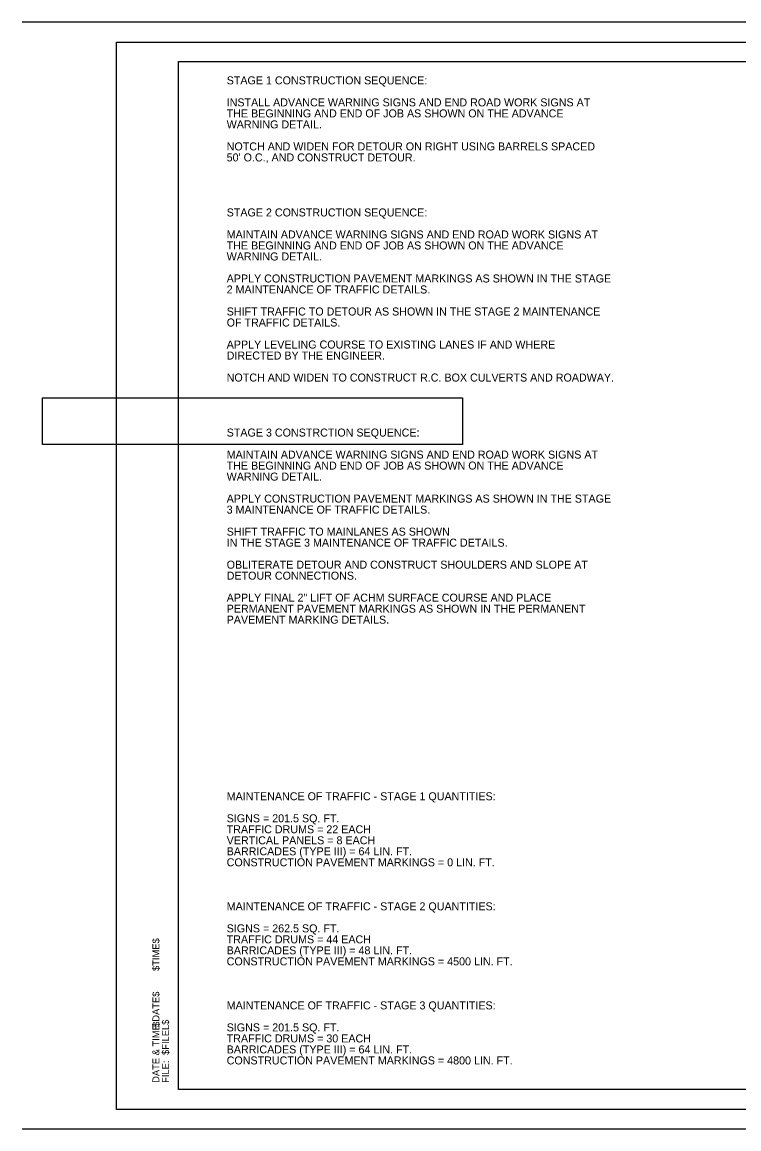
# Model space of a CAD drawing. Extents: x 6125 to 14104, y 8730 to 11067.
# Drawn here: x 6125 to 6841, y 9961 to 11067 of the extents above; entities that cross this region are included whole.
import ezdxf

# ---------------------------------------------------------------- set-up
doc = ezdxf.new("R2010")
doc.units = 0
doc.layers.add('GREEN_TXT', color=7, linetype='Continuous')
doc.layers.add('SEAL-INFO', color=7, linetype='Continuous')

msp = doc.modelspace()

# ---------------------------------------------------------------- linework, layer by layer
msp.add_lwpolyline([(6145.7, 10691.1), (6565.1, 10691.1), (6565.1, 10644.6), (6145.7, 10644.6)], close=True)
at = {"layer": 'GREEN_TXT'}
for p, q in [((7885.4, 11066.7), (6125.4, 11066.7)), ((6281.5, 11027.3), (7862.4, 11027.3)), ((6281.5, 10000), (6281.5, 11027.3)), ((7862.4, 10000), (6281.5, 10000)), ((6125.4, 9960.6), (7885.4, 9960.6))]:
    msp.add_line(p, q, dxfattribs=at)
at = {"layer": 'SEAL-INFO'}
msp.add_lwpolyline([(6219.5, 11046.8), (7886.2, 11046.8), (7886.2, 9980.1), (6219.5, 9980.1)], close=True, dxfattribs=at)

# ---------------------------------------------------------------- texts
for s, p in [('STAGE 1 CONSTRUCTION SEQUENCE:', (6329.7, 11004.5)), ('INSTALL ADVANCE WARNING SIGNS AND END ROAD WORK SIGNS AT ', (6329.7, 10982.5)), ('THE BEGINNING AND END OF JOB AS SHOWN ON THE ADVANCE ', (6329.7, 10971.5)), ('WARNING DETAIL.', (6329.7, 10960.5)), ('NOTCH AND WIDEN FOR DETOUR ON RIGHT USING BARRELS SPACED ', (6329.7, 10938.5)), ("50' O.C., AND CONSTRUCT DETOUR.", (6329.7, 10927.5)), ('STAGE 2 CONSTRUCTION SEQUENCE:', (6329.7, 10872.5)), ('MAINTAIN ADVANCE WARNING SIGNS AND END ROAD WORK SIGNS AT ', (6329.7, 10850.5)), ('THE BEGINNING AND END OF JOB AS SHOWN ON THE ADVANCE ', (6329.7, 10839.5)), ('WARNING DETAIL.', (6329.7, 10828.5)), ('APPLY CONSTRUCTION PAVEMENT MARKINGS AS SHOWN IN THE STAGE ', (6329.7, 10806.5)), ('2 MAINTENANCE OF TRAFFIC DETAILS.', (6329.7, 10795.5)), ('SHIFT TRAFFIC TO DETOUR AS SHOWN IN THE STAGE 2 MAINTENANCE ', (6329.7, 10773.5)), ('OF TRAFFIC DETAILS.', (6329.7, 10762.5)), ('APPLY LEVELING COURSE TO EXISTING LANES IF AND WHERE ', (6329.7, 10740.5)), ('DIRECTED BY THE ENGINEER.', (6329.7, 10729.5)), ('NOTCH AND WIDEN TO CONSTRUCT R.C. BOX CULVERTS AND ROADWAY.', (6329.7, 10707.5)), ('STAGE 3 CONSTRCTION SEQUENCE:', (6329.7, 10652.5)), ('MAINTAIN ADVANCE WARNING SIGNS AND END ROAD WORK SIGNS AT ', (6329.7, 10630.5)), ('THE BEGINNING AND END OF JOB AS SHOWN ON THE ADVANCE ', (6329.7, 10619.5)), ('WARNING DETAIL.', (6329.7, 10608.5)), ('APPLY CONSTRUCTION PAVEMENT MARKINGS AS SHOWN IN THE STAGE ', (6329.7, 10586.5)), ('3 MAINTENANCE OF TRAFFIC DETAILS.', (6329.7, 10575.5)), ('SHIFT TRAFFIC TO MAINLANES AS SHOWN', (6329.7, 10553.5)), ('IN THE STAGE 3 MAINTENANCE OF TRAFFIC DETAILS.', (6329.7, 10542.5)), ('OBLITERATE DETOUR AND CONSTRUCT SHOULDERS AND SLOPE AT ', (6329.7, 10520.5)), ('DETOUR CONNECTIONS.', (6329.7, 10509.5)), ('APPLY FINAL 2" LIFT OF ACHM SURFACE COURSE AND PLACE ', (6329.7, 10487.5)), ('PERMANENT PAVEMENT MARKINGS AS SHOWN IN THE PERMANENT ', (6329.7, 10476.5)), ('PAVEMENT MARKING DETAILS.', (6329.7, 10465.5)), ('MAINTENANCE OF TRAFFIC - STAGE 1 QUANTITIES:', (6329.7, 10289)), ('SIGNS = 201.5 SQ. FT.', (6329.7, 10267)), ('TRAFFIC DRUMS = 22 EACH', (6329.7, 10256)), ('VERTICAL PANELS = 8 EACH', (6329.7, 10245)), ('BARRICADES (TYPE III) = 64 LIN. FT.', (6329.7, 10234)), ('CONSTRUCTION PAVEMENT MARKINGS = 0 LIN. FT.', (6329.7, 10223)), ('MAINTENANCE OF TRAFFIC - STAGE 2 QUANTITIES:', (6329.7, 10179)), ('SIGNS = 262.5 SQ. FT.', (6329.7, 10157)), ('TRAFFIC DRUMS = 44 EACH', (6329.7, 10146)), ('BARRICADES (TYPE III) = 48 LIN. FT.', (6329.7, 10135)), ('CONSTRUCTION PAVEMENT MARKINGS = 4500 LIN. FT.', (6329.7, 10124)), ('MAINTENANCE OF TRAFFIC - STAGE 3 QUANTITIES:', (6329.7, 10080)), ('SIGNS = 201.5 SQ. FT.', (6329.7, 10058)), ('TRAFFIC DRUMS = 30 EACH', (6329.7, 10047)), ('BARRICADES (TYPE III) = 64 LIN. FT.', (6329.7, 10036)), ('CONSTRUCTION PAVEMENT MARKINGS = 4800 LIN. FT.', (6329.7, 10025))]:
    msp.add_text(s, height=8).set_placement(p)
for s, height, p in [('$TIME$', 6.98, (6262.5, 10118.4)), ('$DATE$', 6.98, (6262.5, 10062.5)), ('DATE & TIME:', 6.984, (6262.5, 10006.6)), ('$FILEL$', 6.98, (6272.1, 10034.5)), ('FILE: ', 6.98, (6272.1, 10006.6))]:
    msp.add_text(s, height=height, rotation=90).set_placement(p)

doc.saveas('drawing.dxf')
